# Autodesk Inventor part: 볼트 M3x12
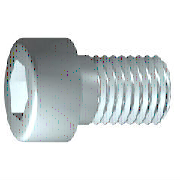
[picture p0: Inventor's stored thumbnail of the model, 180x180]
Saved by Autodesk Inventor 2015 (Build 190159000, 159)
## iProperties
IsCustomPart: 0
Created: 2012-02
Part Number: 볼트 M3x12
Material: 강철, 연강
Description: 6각머리 태핑 나사
Document SubType Name: Modeling
Standard: KS B 1003
Designer: mduedu
Standards Organization: KS
Language: ko-KR
Size Designation: M 3 x 12
Categories: <MemberInstance><Categories><Category DisplayName="조임쇠" InternalName="e4da775c-781d-43d5-af7c-5136215cf5a6" Mnemonic="FSTN"><Category DisplayName="볼트" InternalN
Density: 1 g/cm^3
Appearance: 강철
Author: mduedu
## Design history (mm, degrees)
sketch "스케치1"
  geometry: L1 (-0.867, 0)-(12, 0); L2 (12, 0)-(12, 1.5); L3 (12, 1.5)-(1.25, 1.5); L4 (1.25, 1.5)-(0.943, 1.5); L5 (0.943, 1.5)-(0, 1.5); L6 (0, 1.5)-(0, 2.75); L7 (0, 2.75)-(-3, 2.75); L8 (-3, 2.75)-(-3, 1.443); L9 (-3, 1.443)-(-1.7, 1.443); L10 (-1.7, 1.443)-(-0.867, 0); L11 (-6, 0)-(15, 0) reference; L12 (0, -0.55)-(0, 3.3) reference; L13 (1.25, 1.5)-(0, 1.5)
  constraints: 22 end point, 6 parallel, 2 collinear, 2 perpendicular, 1 horizontal, 1 point on line
  dimensions: "d1" = 10.75 distance from line of L3.end L2 (= GEL); "d2" = 0.30683 distance of L4.end L3.end (computed from GAL); "d3" = 3 distance between parallel lines of L8 L6 (= KOH); "d4" = 1.3 distance of L8.end L9.end (= INTI); "d5" = 60 deg angle of L10 L1; "d6" = 3 diameter of L3 L1 (= GD); "d7" = 3 diameter of L5 L1 (= BDM); "d8" = 2.88675 diameter of L9 L1 (= 1.1547 x SW); "d9" = 5.5 diameter of L7 L1 (= KOD); "d26" = 12 distance between parallel lines of L12 L2 (= NLG)
revolve "본체" sketch "스케치1" stored, may be unused: angle "d10" = 90 deg
sketch "스케치2"
  geometry: L1 (0, -3.85)-(0, 3.85) reference; L2 (-3.85, 0)-(3.85, 0) reference; L3 (1.443, 0)-(0.722, -1.25); L4 (0.722, -1.25)-(-0.722, -1.25); L5 (-0.722, -1.25)-(-1.443, 0); L6 (-1.443, 0)-(-0.722, 1.25); L7 (-0.722, 1.25)-(0.722, 1.25); L8 (0.722, 1.25)-(1.443, 0); 2 further points
  constraints: 12 end point, 1 coincident, 1 horizontal alignment, 1 point on line, 12 other
extrude "슬롯" join sketch "스케치2" stored distance "d11" = 10; taper "d12" = 0 deg
workplane "Work Plane1"
fillet "Fillet2" dims "d30" = 0.1 (= R)
body "Solid1"
fillet "모깎기1" dims "d17" = 0.3 (= RR)
feature "스레드" dims "d13" = 10.75 (= GEL), "d14" = 0
chamfer "모따기1" distance "d15" = 0.30673 (= -0.5 x SPD + 0.5 x GD); stored, may be unused: second distance "d16" = 0.30673 (= GUL), angle "d27" = 45 deg
other parameters: "GD" = 3 (= NND) [user parameter; used in 2 equation terms], "NLG" = 12 [user parameter; used in 1 equation term], "GEL" = 10.75 [user parameter; used in 2 equation terms], "KOD" = 5.5 [user parameter; used in 1 equation term], "KOH" = 3 [user parameter; used in 1 equation term], "INTI" = 1.3 [user parameter; used in 1 equation term], "GAL" = 0.30673 (= 0.61345 x PTC) [user parameter; used in 1 equation term], "GUL" = 0.30673 (= 0.61345 x PTC) [user parameter; used in 1 equation term], "BDM" = 3 (= NND) [user parameter; used in 1 equation term], "SW" = 2.5 [user parameter; used in 2 equation terms], "RR" = 0.3 [user parameter; used in 1 equation term], "SPD" = 2.38655 (= NND - 1.2269 x PTC) [user parameter; used in 1 equation term], "d19" = 0, "d28" = 0, "d29" = 0, "R" = 0.1 [user parameter; used in 1 equation term], "PHH" = 0.1 [user parameter], "GD1" = 2.38655 (= THREADDIA - 1.2269 x PTC) [user parameter], "THREADDIA" = 3 [user parameter; used in 1 equation term], "FAWI" = 45 deg [user parameter], "PTC" = 0.5 [user parameter; used in 5 equation terms], "NND" = 3 [user parameter; used in 3 equation terms], "TOA" = 30 deg [user parameter], "E0" = 2.8875 (= 1.155 x SW) [user parameter]
